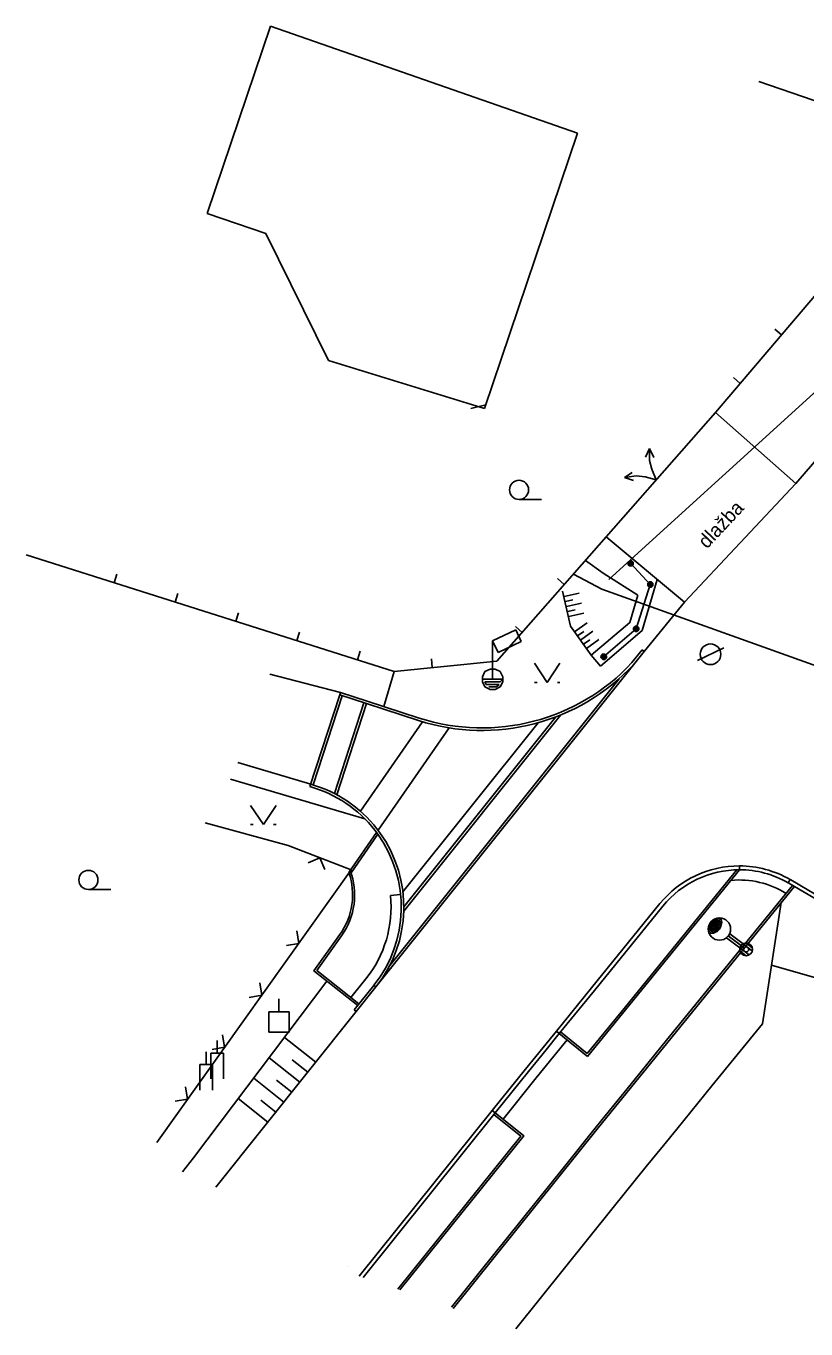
# Model space of a CAD drawing. Extents: x -559554 to -559082, y -1075950 to -1075150.
# Drawn here: x -559553.9 to -559523.4, y -1075949.9 to -1075898.9 of the extents above; entities that cross this region are included whole.
import ezdxf

# ---------------------------------------------------------------- set-up
doc = ezdxf.new("R2010")
doc.units = 0
for name, color, linetype in [('_kom_5 - Lampa v', 7, 'Continuous'), ('Implicitní', 7, 'Continuous'), ('kl', 7, 'Continuous'), ('Legenda', 7, 'Continuous'), ('ODKAZY', 7, 'Continuous'), ('PF', 7, 'Continuous'), ('popis', 7, 'Continuous'), ('Ramecek_rozpiska', 7, 'Continuous'), ('sklonovnik', 7, 'Continuous'), ('trasa', 7, 'Continuous'), ('VRSTVA_1', 7, 'Continuous')]:
    doc.layers.add(name, color=color, linetype=linetype)

# ---------------------------------------------------------------- blocks, each defined once
blk = doc.blocks.new('POINT')
at = {"layer": 'Implicitní'}
blk.add_line((0, 0), (0, 0), dxfattribs=at)
blk = doc.blocks.new('VO_10')
at = {"layer": '_kom_5 - Lampa v'}
for p, q in [((-0.228, 0.102), (0.228, 0.102)), ((-0.147, 0.202), (0.147, 0.202)), ((0.877, 0), (0.1, 0)), ((0.883, 0.1), (0.229, 0.1)), ((0.25, 0), (0.877, 0)), ((1.315, 0), (1.752, 0)), ((1.319, 0.062), (1.748, 0.062)), ((1.333, 0.125), (1.734, 0.125)), ((1.357, 0.187), (1.71, 0.187)), ((1.393, 0.25), (1.674, 0.25)), ((1.446, 0.312), (1.621, 0.312)), ((-0.23, -0.098), (0.23, -0.098)), ((-0.153, -0.198), (0.153, -0.198)), ((0.883, -0.1), (0.229, -0.1)), ((1.319, -0.063), (1.748, -0.063)), ((1.333, -0.125), (1.734, -0.125)), ((1.357, -0.188), (1.71, -0.188)), ((1.393, -0.25), (1.674, -0.25)), ((1.446, -0.313), (1.621, -0.313))]:
    blk.add_line(p, q, dxfattribs=at)
for centre, radius in [((0, 0), 0.25), ((0, 0), 0.1), ((1.315, 0), 0.438)]:
    blk.add_circle(centre, radius, dxfattribs=at)
blk.add_arc((1.752, 0), 0.437, 119.9999, 240, dxfattribs=at)

msp = doc.modelspace()

# ---------------------------------------------------------------- linework, layer by layer
at = {"layer": 'kl'}
for p, q in [((-559517.919, -1075903.519), (-559525.238, -1075901.03)), ((-559526.94, -1075913.989), (-559518.715, -1075904.329)), ((-559524.346, -1075910.943), (-559524.613, -1075910.716)), ((-559531.119, -1075920.521), (-559521.405, -1075911.693)), ((-559519.735, -1075912.043), (-559523.791, -1075916.765)), ((-559525.967, -1075912.846), (-559526.234, -1075912.62)), ((-559536.523, -1075913.826), (-559535.936, -1075913.685)), ((-559531.225, -1075918.855), (-559526.94, -1075913.989)), ((-559523.791, -1075916.765), (-559526.94, -1075913.989)), ((-559529.515, -1075915.4), (-559529.672, -1075915.729)), ((-559529.521, -1075915.861), (-559529.515, -1075915.4)), ((-559529.515, -1075915.4), (-559529.352, -1075915.744)), ((-559530.507, -1075916.526), (-559530.2, -1075916.329)), ((-559529.428, -1075916.21), (-559529.521, -1075915.861)), ((-559529.26, -1075916.624), (-559529.428, -1075916.21)), ((-559530.507, -1075916.526), (-559530.05, -1075916.462)), ((-559530.507, -1075916.526), (-559530.145, -1075916.645)), ((-559530.05, -1075916.462), (-559529.693, -1075916.51)), ((-559529.693, -1075916.51), (-559529.26, -1075916.624)), ((-559523.791, -1075916.765), (-559528.153, -1075921.415)), ((-559534.631, -1075917.389), (-559533.756, -1075917.389)), ((-559535.502, -1075923.727), (-559531.225, -1075918.855)), ((-559528.153, -1075921.415), (-559531.225, -1075918.855)), ((-559539.526, -1075924.12), (-559553.947, -1075919.562)), ((-559532.032, -1075919.774), (-559531.337, -1075920.278)), ((-559530.359, -1075919.844), (-559530.309, -1075919.794)), ((-559530.359, -1075919.944), (-559530.359, -1075919.844)), ((-559530.309, -1075919.794), (-559530.209, -1075919.794)), ((-559530.309, -1075919.944), (-559530.309, -1075919.844)), ((-559530.309, -1075919.844), (-559530.209, -1075919.844)), ((-559530.309, -1075919.944), (-559530.209, -1075919.844)), ((-559530.259, -1075919.894), (-559529.49, -1075920.721)), ((-559530.209, -1075919.794), (-559530.159, -1075919.844)), ((-559530.209, -1075919.844), (-559530.209, -1075919.944)), ((-559530.159, -1075919.844), (-559530.159, -1075919.944)), ((-559550.491, -1075920.654), (-559550.386, -1075920.32)), ((-559532.504, -1075920.313), (-559531.39, -1075920.901)), ((-559531.337, -1075920.278), (-559529.976, -1075921.143)), ((-559530.309, -1075919.994), (-559530.359, -1075919.944)), ((-559530.209, -1075919.944), (-559530.309, -1075919.944)), ((-559530.209, -1075919.994), (-559530.309, -1075919.994)), ((-559530.159, -1075919.944), (-559530.209, -1075919.994)), ((-559532.863, -1075920.721), (-559533.126, -1075920.49)), ((-559531.39, -1075920.901), (-559520.012, -1075924.983)), ((-559529.49, -1075920.721), (-559530.043, -1075922.456)), ((-559529.219, -1075920.527), (-559529.81, -1075922.516)), ((-559529.59, -1075920.671), (-559529.54, -1075920.621)), ((-559529.59, -1075920.771), (-559529.59, -1075920.671)), ((-559529.54, -1075920.821), (-559529.59, -1075920.771)), ((-559529.54, -1075920.621), (-559529.44, -1075920.621)), ((-559529.54, -1075920.771), (-559529.54, -1075920.671)), ((-559529.54, -1075920.671), (-559529.44, -1075920.671)), ((-559529.54, -1075920.771), (-559529.44, -1075920.671)), ((-559529.44, -1075920.771), (-559529.54, -1075920.771)), ((-559529.44, -1075920.821), (-559529.54, -1075920.821)), ((-559529.44, -1075920.621), (-559529.39, -1075920.671)), ((-559529.44, -1075920.671), (-559529.44, -1075920.771)), ((-559529.39, -1075920.771), (-559529.44, -1075920.821)), ((-559529.39, -1075920.671), (-559529.39, -1075920.771)), ((-559548.108, -1075921.408), (-559548.002, -1075921.074)), ((-559532.616, -1075922.347), (-559532.932, -1075920.983)), ((-559532.274, -1075921.056), (-559532.858, -1075921.192)), ((-559532.521, -1075921.319), (-559532.813, -1075921.387)), ((-559532.183, -1075921.446), (-559532.768, -1075921.582)), ((-559529.976, -1075921.143), (-559530.291, -1075922.203)), ((-559528.153, -1075921.415), (-559529.728, -1075923.339)), ((-559545.724, -1075922.161), (-559545.618, -1075921.827)), ((-559532.43, -1075921.709), (-559532.723, -1075921.776)), ((-559532.093, -1075921.836), (-559532.678, -1075921.971)), ((-559534.513, -1075922.6), (-559534.776, -1075922.369)), ((-559531.802, -1075923.492), (-559532.616, -1075922.347)), ((-559531.967, -1075922.225), (-559532.456, -1075922.572)), ((-559530.291, -1075922.203), (-559531.802, -1075923.492)), ((-559530.043, -1075922.456), (-559531.317, -1075923.546)), ((-559530.15, -1075922.487), (-559530.148, -1075922.417)), ((-559530.148, -1075922.417), (-559530.074, -1075922.349)), ((-559530.114, -1075922.453), (-559530.04, -1075922.385)), ((-559530.045, -1075922.527), (-559530.114, -1075922.453)), ((-559530.114, -1075922.453), (-559529.972, -1075922.458)), ((-559530.074, -1075922.349), (-559530.004, -1075922.351)), ((-559529.972, -1075922.458), (-559530.045, -1075922.527)), ((-559530.04, -1075922.385), (-559529.972, -1075922.458)), ((-559530.004, -1075922.351), (-559529.936, -1075922.424)), ((-559529.936, -1075922.424), (-559529.938, -1075922.495)), ((-559543.34, -1075922.915), (-559543.235, -1075922.581)), ((-559534.763, -1075922.5), (-559535.666, -1075922.931)), ((-559535.666, -1075922.931), (-559535.666, -1075924.431)), ((-559535.666, -1075922.931), (-559535.451, -1075923.382)), ((-559535.451, -1075923.382), (-559534.548, -1075922.952)), ((-559534.548, -1075922.952), (-559534.763, -1075922.5)), ((-559532.096, -1075922.561), (-559532.34, -1075922.735)), ((-559531.735, -1075922.551), (-559532.225, -1075922.898)), ((-559531.864, -1075922.887), (-559532.109, -1075923.061)), ((-559531.504, -1075922.877), (-559531.993, -1075923.224)), ((-559529.81, -1075922.516), (-559531.446, -1075923.911)), ((-559530.082, -1075922.561), (-559530.15, -1075922.487)), ((-559530.011, -1075922.563), (-559530.082, -1075922.561)), ((-559529.938, -1075922.495), (-559530.011, -1075922.563)), ((-559540.956, -1075923.668), (-559540.851, -1075923.334)), ((-559531.802, -1075923.492), (-559531.446, -1075923.911)), ((-559531.421, -1075923.507), (-559531.348, -1075923.439)), ((-559531.387, -1075923.543), (-559531.314, -1075923.475)), ((-559531.348, -1075923.439), (-559531.277, -1075923.441)), ((-559531.314, -1075923.475), (-559531.246, -1075923.548)), ((-559531.277, -1075923.441), (-559531.209, -1075923.514)), ((-559527.647, -1075923.695), (-559526.611, -1075923.206)), ((-559539.526, -1075924.12), (-559535.502, -1075923.727)), ((-559538.033, -1075923.974), (-559538.067, -1075923.626)), ((-559534.028, -1075923.806), (-559533.528, -1075924.556)), ((-559533.528, -1075924.556), (-559533.028, -1075923.806)), ((-559531.424, -1075923.577), (-559531.421, -1075923.507)), ((-559531.356, -1075923.651), (-559531.424, -1075923.577)), ((-559531.319, -1075923.617), (-559531.387, -1075923.543)), ((-559531.387, -1075923.543), (-559531.246, -1075923.548)), ((-559531.285, -1075923.653), (-559531.356, -1075923.651)), ((-559531.246, -1075923.548), (-559531.319, -1075923.617)), ((-559531.212, -1075923.585), (-559531.285, -1075923.653)), ((-559531.209, -1075923.514), (-559531.212, -1075923.585)), ((-559541.628, -1075924.947), (-559544.395, -1075924.232)), ((-559539.526, -1075924.12), (-559539.935, -1075925.497)), ((-559536.066, -1075924.331), (-559535.966, -1075924.131)), ((-559536.066, -1075924.531), (-559536.066, -1075924.331)), ((-559536.066, -1075924.431), (-559535.266, -1075924.431)), ((-559535.966, -1075924.131), (-559535.766, -1075924.031)), ((-559535.766, -1075924.031), (-559535.566, -1075924.031)), ((-559535.566, -1075924.031), (-559535.366, -1075924.131)), ((-559535.366, -1075924.131), (-559535.266, -1075924.331)), ((-559535.266, -1075924.431), (-559535.366, -1075924.531)), ((-559535.266, -1075924.331), (-559535.266, -1075924.531)), ((-559535.966, -1075924.731), (-559536.066, -1075924.531)), ((-559535.366, -1075924.531), (-559535.966, -1075924.531)), ((-559535.966, -1075924.531), (-559535.916, -1075924.631)), ((-559535.766, -1075924.831), (-559535.966, -1075924.731)), ((-559535.916, -1075924.631), (-559535.416, -1075924.631)), ((-559535.516, -1075924.731), (-559535.816, -1075924.731)), ((-559535.566, -1075924.831), (-559535.766, -1075924.831)), ((-559535.366, -1075924.731), (-559535.566, -1075924.831)), ((-559535.416, -1075924.631), (-559535.516, -1075924.731)), ((-559535.266, -1075924.531), (-559535.366, -1075924.731)), ((-559534.028, -1075924.556), (-559533.928, -1075924.556)), ((-559533.128, -1075924.556), (-559533.028, -1075924.556)), ((-559542.795, -1075928.535), (-559545.646, -1075927.69)), ((-559540.669, -1075929.901), (-559545.933, -1075928.34)), ((-559545.148, -1075929.37), (-559544.648, -1075930.12)), ((-559544.648, -1075930.12), (-559544.148, -1075929.37)), ((-559543.675, -1075930.945), (-559546.926, -1075930.053)), ((-559545.148, -1075930.12), (-559545.048, -1075930.12)), ((-559544.248, -1075930.12), (-559544.148, -1075930.12)), ((-559541.207, -1075931.897), (-559543.675, -1075930.945)), ((-559542.441, -1075931.421), (-559542.893, -1075931.621)), ((-559542.24, -1075931.873), (-559542.441, -1075931.421)), ((-559548.828, -1075942.568), (-559541.207, -1075931.897)), ((-559551.502, -1075932.663), (-559550.627, -1075932.663)), ((-559543.26, -1075934.772), (-559543.341, -1075934.283)), ((-559543.748, -1075934.853), (-559543.26, -1075934.772)), ((-559524.741, -1075935.629), (-559522.692, -1075936.214)), ((-559542.159, -1075936.25), (-559547.384, -1075943.164)), ((-559544.713, -1075936.806), (-559544.794, -1075936.318)), ((-559545.201, -1075936.887), (-559544.713, -1075936.806)), ((-559544.04, -1075937.447), (-559544.04, -1075936.947)), ((-559541.008, -1075937.434), (-559546.507, -1075944.321)), ((-559544.44, -1075937.447), (-559543.64, -1075937.447)), ((-559544.44, -1075938.247), (-559544.44, -1075937.447)), ((-559543.64, -1075937.447), (-559543.64, -1075938.247)), ((-559543.64, -1075938.247), (-559544.44, -1075938.247)), ((-559546.456, -1075939.07), (-559546.456, -1075938.57)), ((-559546.166, -1075938.841), (-559546.247, -1075938.352)), ((-559542.6, -1075939.428), (-559543.823, -1075938.452)), ((-559546.889, -1075939.514), (-559546.889, -1075939.014)), ((-559546.706, -1075940.07), (-559546.706, -1075939.07)), ((-559546.706, -1075939.07), (-559546.206, -1075939.07)), ((-559546.654, -1075938.922), (-559546.166, -1075938.841)), ((-559546.206, -1075939.07), (-559546.206, -1075940.07)), ((-559543.224, -1075940.21), (-559544.426, -1075939.25)), ((-559547.139, -1075940.514), (-559547.139, -1075939.514)), ((-559547.139, -1075939.514), (-559546.639, -1075939.514)), ((-559546.639, -1075939.514), (-559546.639, -1075940.514)), ((-559542.912, -1075939.819), (-559543.519, -1075939.335)), ((-559543.848, -1075940.991), (-559545.029, -1075940.048)), ((-559543.536, -1075940.601), (-559544.132, -1075940.125)), ((-559547.619, -1075940.875), (-559547.7, -1075940.387)), ((-559544.472, -1075941.773), (-559545.632, -1075940.846)), ((-559548.107, -1075940.956), (-559547.619, -1075940.875)), ((-559544.16, -1075941.382), (-559544.746, -1075940.915)), ((-559547.384, -1075943.164), (-559547.823, -1075943.723))]:
    msp.add_line(p, q, dxfattribs=at)
for centre, radius in [((-559534.632, -1075917.015), 0.375), ((-559527.13, -1075923.451), 0.405), ((-559551.503, -1075932.288), 0.375)]:
    msp.add_circle(centre, radius, dxfattribs=at)
at = {"layer": 'Legenda'}
for p, q in [((-559540.243, -1075936.477), (-559529.728, -1075923.339)), ((-559530.208, -1075923.779), (-559529.808, -1075923.28)), ((-559529.728, -1075923.339), (-559529.808, -1075923.28)), ((-559539.699, -1075935.638), (-559530.711, -1075924.407)), ((-559541.659, -1075925.042), (-559541.628, -1075924.947)), ((-559542.826, -1075928.63), (-559541.659, -1075925.042)), ((-559542.7, -1075928.566), (-559541.564, -1075925.073)), ((-559541.864, -1075928.905), (-559540.708, -1075925.351)), ((-559541.774, -1075928.952), (-559540.613, -1075925.382)), ((-559539.149, -1075933.51), (-559533, -1075925.827)), ((-559539.146, -1075933.347), (-559533.188, -1075925.902)), ((-559525.996, -1075931.889), (-559525.995, -1075931.739)), ((-559524.091, -1075932.401), (-559524.015, -1075932.271)), ((-559541.086, -1075937.371), (-559540.321, -1075936.415)), ((-559541.008, -1075937.434), (-559540.243, -1075936.477)), ((-559540.321, -1075936.415), (-559540.243, -1075936.477)), ((-559541.008, -1075937.434), (-559541.086, -1075937.371)), ((-559533.171, -1075938.205), (-559533.055, -1075938.299)), ((-559535.684, -1075941.314), (-559535.567, -1075941.408))]:
    msp.add_line(p, q, dxfattribs=at)
for points in [[(-559541.628, -1075924.947), (-559540.582, -1075925.287), (-559538.542, -1075925.95)], [(-559541.659, -1075925.042), (-559540.613, -1075925.382), (-559538.573, -1075926.045)], [(-559542.603, -1075928.597), (-559542.795, -1075928.535)], [(-559542.634, -1075928.693), (-559542.826, -1075928.63)], [(-559523.854, -1075932.553), (-559531.536, -1075941.993), (-559537.216, -1075949.072)], [(-559522.487, -1075933.338), (-559524.065, -1075932.416)], [(-559522.411, -1075933.209), (-559523.99, -1075932.286)], [(-559529.111, -1075933.215), (-559531.798, -1075936.517), (-559533.171, -1075938.205)], [(-559528.995, -1075933.309), (-559531.682, -1075936.612), (-559533.055, -1075938.299)], [(-559533.171, -1075938.205), (-559533.692, -1075938.844), (-559534.382, -1075939.693), (-559535.684, -1075941.314)], [(-559533.055, -1075938.299), (-559533.576, -1075938.939), (-559534.266, -1075939.787), (-559535.567, -1075941.408)], [(-559535.684, -1075941.314), (-559540.894, -1075947.808)], [(-559535.567, -1075941.408), (-559540.743, -1075947.858)]]:
    msp.add_lwpolyline(points, dxfattribs=at)
for centre, radius, start, end in [((-559536.085, -1075918.3), 8.135, 252.1939, 317.0077), ((-559536.085, -1075918.3), 8.035, 252.1952, 317.0077), ((-559544.146, -1075933.353), 5, 35.6277, 72.0208), ((-559544.146, -1075933.353), 4.9, 35.6277, 72.0208), ((-559544.146, -1075933.353), 4.9, 321.3299, 35.6277), ((-559544.146, -1075933.353), 5, 321.3299, 35.6277), ((-559526.008, -1075935.739), 4, 89.8098, 140.8649), ((-559526.008, -1075935.739), 3.85, 89.8098, 140.8649), ((-559526.008, -1075935.739), 3.85, 60.1322, 89.9006), ((-559526.008, -1075935.739), 4, 60.1155, 89.8098), ((-559526.008, -1075935.739), 3.85, 59.6888, 60.1322), ((-559526.008, -1075935.739), 4, 59.6888, 60.1155)]:
    msp.add_arc(centre, radius, start, end, dxfattribs=at)
at = {"layer": 'PF'}
for p, q in [((-559544.367, -1075898.853), (-559546.85, -1075906.189)), ((-559544.367, -1075898.853), (-559532.337, -1075903.051)), ((-559532.337, -1075903.051), (-559535.986, -1075913.831)), ((-559544.559, -1075906.979), (-559546.85, -1075906.189)), ((-559544.559, -1075906.979), (-559542.095, -1075911.948)), ((-559542.095, -1075911.948), (-559535.986, -1075913.831))]:
    msp.add_line(p, q, dxfattribs=at)
at = {"layer": 'popis'}
msp.add_lwpolyline([(-559524.357, -1075933.172), (-559525.098, -1075937.916), (-559527.082, -1075940.355), (-559528.455, -1075942.042), (-559528.976, -1075942.682), (-559529.653, -1075943.514), (-559530.942, -1075945.12), (-559534.753, -1075949.869)], dxfattribs=at)
at = {"layer": 'Ramecek_rozpiska'}
for p, q in [((-559540.85, -1075929.594), (-559538.416, -1075926.094)), ((-559540.153, -1075930.344), (-559537.365, -1075926.334)), ((-559539.183, -1075932.752), (-559533.884, -1075926.132))]:
    msp.add_line(p, q, dxfattribs=at)
for points in [[(-559539.271, -1075932.863), (-559539.669, -1075932.903)], [(-559540.633, -1075936.165), (-559541.216, -1075936.894)], [(-559532.745, -1075938.552), (-559533.265, -1075939.192), (-559533.955, -1075940.039), (-559535.255, -1075941.659)]]:
    msp.add_lwpolyline(points, dxfattribs=at)
for centre, radius, start, end in [((-559526.008, -1075935.739), 3.45, 57.8585, 95.4083), ((-559544.146, -1075933.353), 4.5, 321.3299, 5.7452)]:
    msp.add_arc(centre, radius, start, end, dxfattribs=at)
at = {"layer": 'sklonovnik'}
for p, q in [((-559541.303, -1075931.997), (-559540.213, -1075930.431)), ((-559541.214, -1075932.009), (-559540.164, -1075930.499)), ((-559526.1, -1075931.89), (-559530.635, -1075937.464)), ((-559525.996, -1075931.889), (-559530.573, -1075937.515)), ((-559540.903, -1075937.142), (-559542.558, -1075935.832)), ((-559530.635, -1075937.464), (-559531.957, -1075939.089)), ((-559530.573, -1075937.515), (-559531.946, -1075939.202)), ((-559531.957, -1075939.089), (-559533.005, -1075938.237)), ((-559531.946, -1075939.202), (-559533.055, -1075938.299))]:
    msp.add_line(p, q, dxfattribs=at)
for points in [[(-559523.916, -1075932.503), (-559529.022, -1075938.777), (-559530.395, -1075940.464), (-559530.915, -1075941.104), (-559531.598, -1075941.943), (-559532.891, -1075943.555), (-559537.278, -1075949.022)], [(-559540.953, -1075937.205), (-559542.667, -1075935.848), (-559541.652, -1075934.428)], [(-559542.558, -1075935.832), (-559541.587, -1075934.474)], [(-559535.617, -1075941.471), (-559534.564, -1075942.316), (-559539.379, -1075948.316)], [(-559535.567, -1075941.408), (-559534.451, -1075942.303), (-559539.298, -1075948.343)]]:
    msp.add_lwpolyline(points, dxfattribs=at)
for radius, end in [(2.67, 19.2012), (2.75, 20.4025)]:
    msp.add_arc((-559543.824, -1075932.875), radius, 324.4379, end, dxfattribs=at)

# ---------------------------------------------------------------- block references
at = {"layer": 'ODKAZY', "rotation": 0.39164048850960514}
for p in [(-559541.153, -1075931.782), (-559539.616, -1075935.751)]:
    msp.add_blockref('POINT', p, dxfattribs=at)
at = {"layer": 'ODKAZY'}
msp.add_blockref('POINT', (-559541.351, -1075947.429), dxfattribs=at)
at = {"layer": 'trasa', "rotation": 0.39164048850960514}
for p in [(-559542.344, -1075928.71), (-559539.627, -1075935.601)]:
    msp.add_blockref('POINT', p, dxfattribs=at)
at = {"layer": 'trasa'}
msp.add_blockref('POINT', (-559527.771, -1075934.009), dxfattribs=at)
at = {"layer": 'VRSTVA_1', "rotation": 142.75643482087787}
msp.add_blockref('VO_10', (-559525.735, -1075935.006), dxfattribs=at)

# ---------------------------------------------------------------- texts
at = {"layer": 'kl'}
msp.add_text('dlažba', height=0.5525, rotation=46.8258, dxfattribs=at).set_placement((-559527.273, -1075919.347))

doc.saveas('drawing.dxf')
